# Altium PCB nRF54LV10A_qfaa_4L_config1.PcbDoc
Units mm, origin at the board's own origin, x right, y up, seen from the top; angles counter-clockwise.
Board outline 14.6 x 13 mm, 4 copper layers (Top Layer, Mid-Layer 1, Mid-Layer 2, Bottom Layer), stack 1.64 mm thick; 20 components, 48 nets, 89 pads, 52 vias.
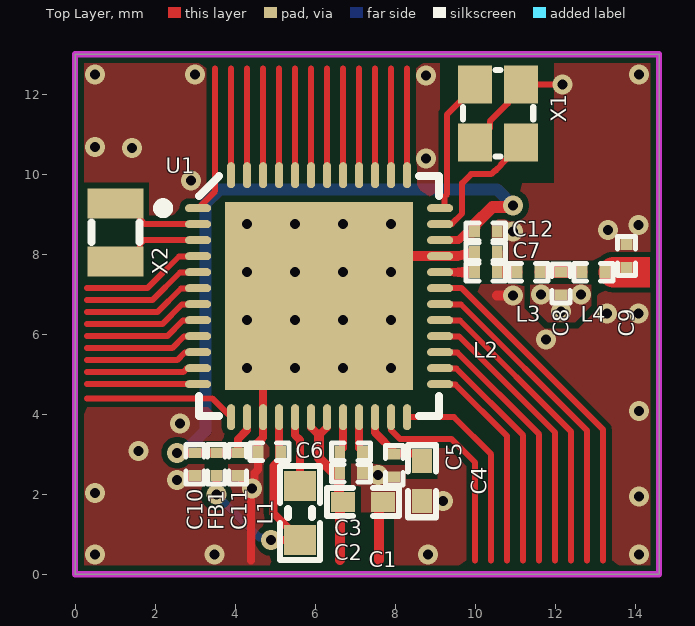
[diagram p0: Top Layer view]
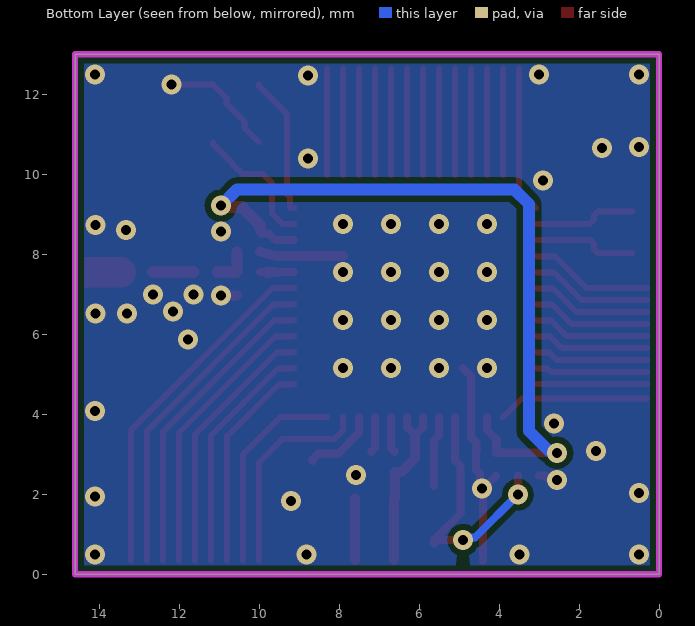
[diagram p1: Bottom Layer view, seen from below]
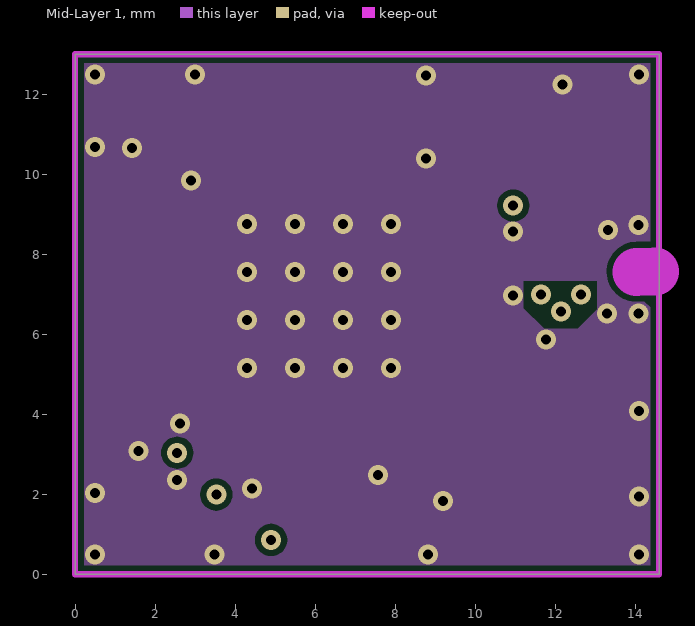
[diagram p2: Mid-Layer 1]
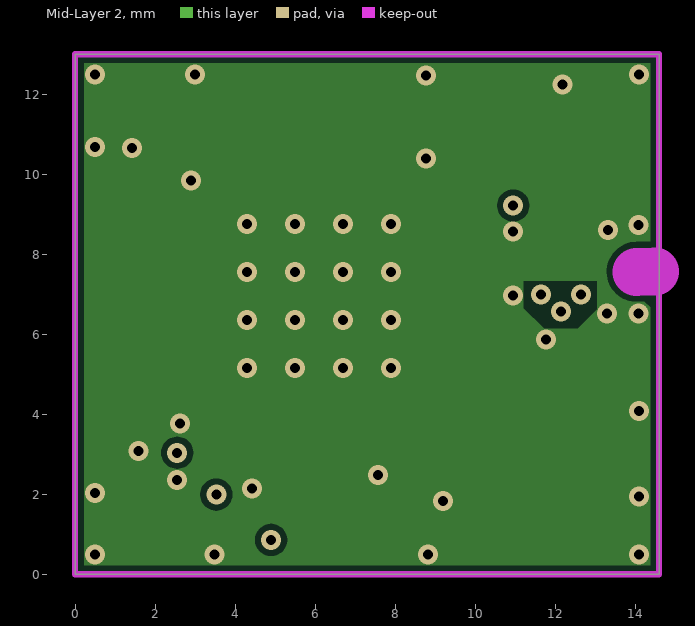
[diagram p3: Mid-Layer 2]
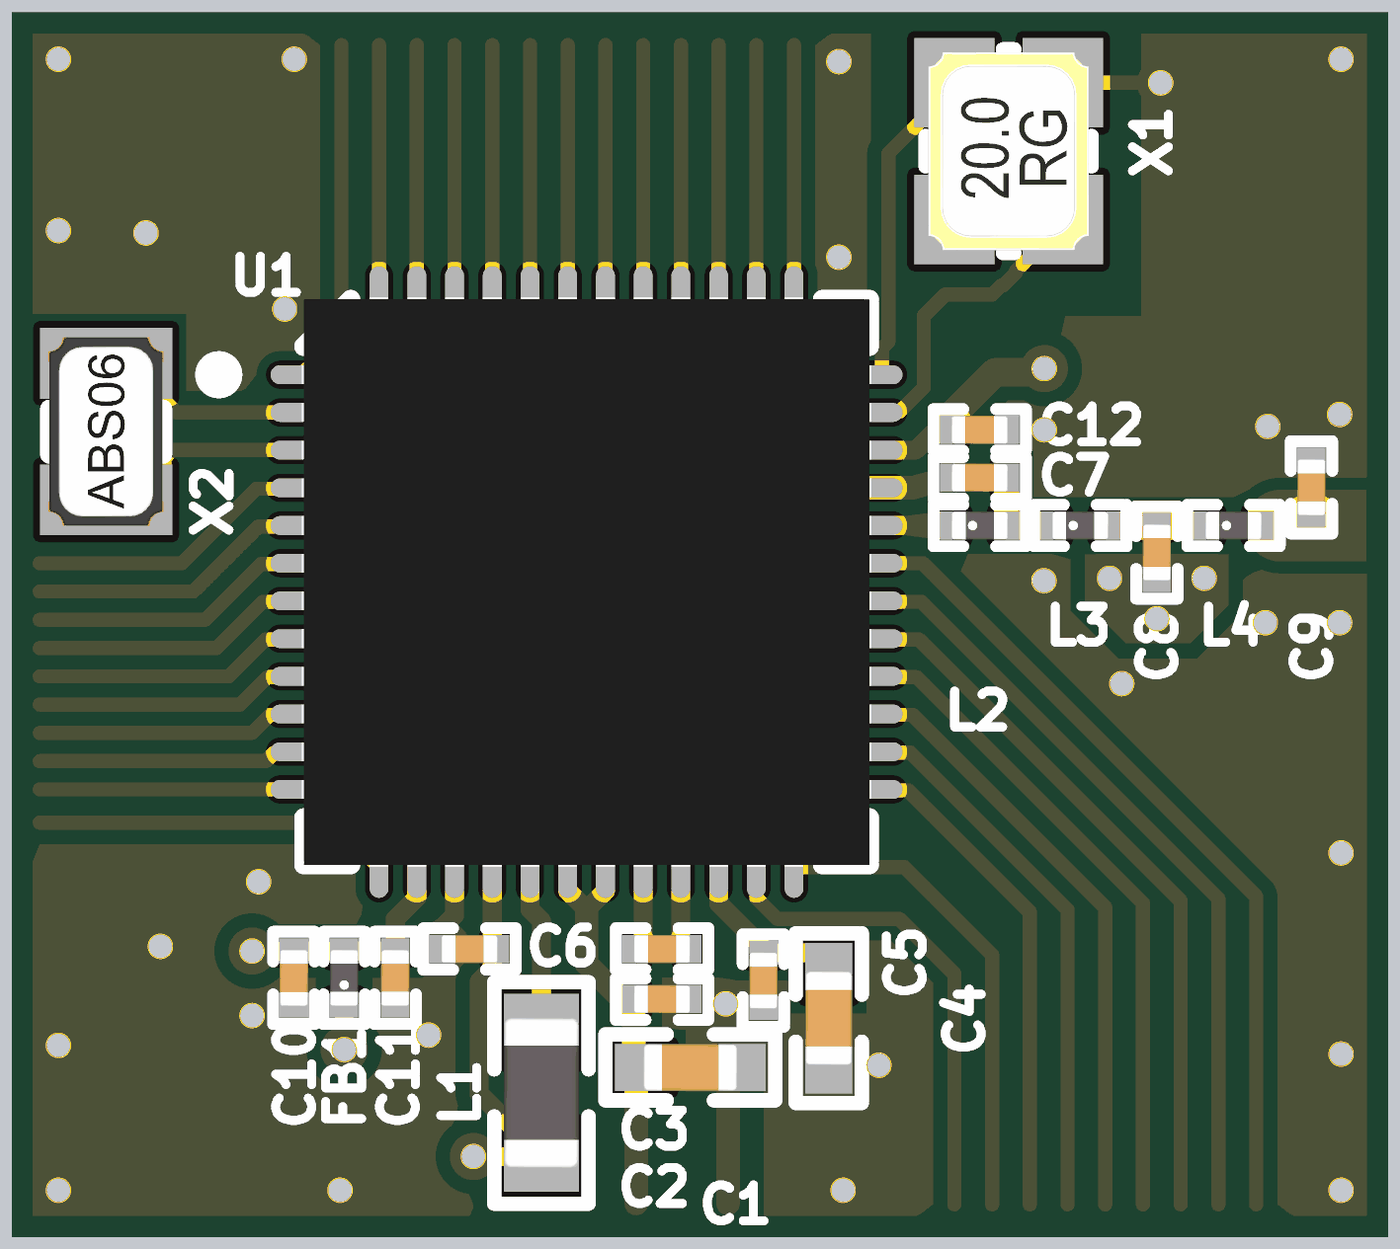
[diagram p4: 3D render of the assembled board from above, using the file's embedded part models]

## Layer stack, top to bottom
Top Solder: solder mask 0.0254, SM-003, Dk 4
Top Layer: signal copper 0.035
Dielectric 1: prepreg 0.1, PP-006, Dk 4.1
Mid-Layer 1: signal copper 0.035
Dielectric1: core 1.3, FR-4, Dk 4.8
Mid-Layer 2: signal copper 0.035
Dielectric 2: prepreg 0.1, PP-006, Dk 4.1
Bottom Layer: signal copper 0.035
Bottom Solder: solder mask 0.0254, SM-003, Dk 4

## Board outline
0,0 14.6,0 14.6,13 0,13

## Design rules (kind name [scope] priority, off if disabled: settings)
Clearance Polygon_ANT [(InNamedPolygon('Mid-Layer1-GND')) or IsFill or IsRegion vs InNet('RF')] p1: gap=0.127 ignorepadtopadclearanceinfootprint=FALSE
Clearance Polygon [(InNamedPolygon('Mid-Layer1-GND')) or (InNamedPolygon('Bottom_Layer-GND'))] p2: gap=0.15 ignorepadtopadclearanceinfootprint=FALSE
Clearance [All] p3: gap=0.15 ignorepadtopadclearanceinfootprint=FALSE
ComponentClearance [All] p1 off: gap=0.254 collisioncheckmode=3 verticalgap=0.254 showdistances=FALSE
FabricationTestPointUsage TestPointUsage [All] p1: valid=0 allowmultiple=FALSE
FabricationTestpoint Testpoint [All] p1: side=3 testpointundercomponent=TRUE minsize=1.016 maxsize=2.54 preferedsize=1.524 minholesize=0 maxholesize=1.016 preferedholesize=0.813 testpointgrid=0.025 allowsidetop=TRUE allowsidebottom=TRUE usegrid=TRUE gridtolerance=0
Height [All] p1 off: minheight=0 maxheight=25.4 prefheight=12.7
HoleSize [All] p1: absolutevalues=TRUE maxlimit=4 minlimit=0.2 maxpercent=80.000 minpercent=20.000
HoleToHoleClearance [All] p1: gap=0.36 allowstackedmicrovias=FALSE
MinimumAnnularRing [All] p1 off: minimumring=0.152
PolygonConnect PolygonConnect_GND_VIAs [isVia and innet(gnd)] p1: connectstyle=Direct reliefconductorwidth=0.254 reliefentries=4 polygonreliefangle="90 Angle" airgapwidth=0.254
PolygonConnect PolygonQFNConnect [HasFootprint('QFN40P600X600X90-48N')] p2: connectstyle=Relief reliefconductorwidth=0.254 reliefentries=4 polygonreliefangle="90 Angle" airgapwidth=0.25
PolygonConnect PolygonDirectConnect [All] p3: connectstyle=Direct reliefconductorwidth=0.254 reliefentries=4 polygonreliefangle="90 Angle" airgapwidth=0.25
RoutingVias [All] p1: holewidth=0.406 width=0.813 viastyle="Through Hole" minholewidth=0.2 minwidth=0.2 maxholewidth=0.711 maxwidth=1.27
SilkToSolderMaskClearance SilkscreenOverComponentPads [IsPad] p1: minsilkscreentomaskgap=0.254 clearancetoexposedcopper=TRUE
SolderMaskExpansion SolderMaskExpansion_via [IsVia] p1: expansion=0.102 istentingtop=TRUE
SolderMaskExpansion [All] p2: expansion=0.076 istentingtop=FALSE
Width [All] p1: maxlimit=2.54 minlimit=0.125 preferedwidth=0.15 midlayer1_minwidth=0.15 midlayer2_minwidth=0.15 minimp=50.000000 maximp=50.000000 favimp=50.000000
23 further rules are at their usual default settings.

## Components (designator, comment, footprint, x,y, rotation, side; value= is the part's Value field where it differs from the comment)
C1 "10µF" CAPC1005X04L 7.2,1.803 r180 top
C2 "100nF" CAPC0603X03L_C#1 6.9,2.528 r180 top
C3 "1.0µF" CAPC0603X03L_C#2 6.9,3.06 r0 top
C4 "10µF" CAPC1005X04L 8.668,2.326 r90 top
C5 "100nF" CAPC0603X03L_C#3 7.975,2.725 r270 top
C6 "4.7µF" CAPC0603X03L_C#1 4.859,3.06 r0 top
C7 "1.5pF" CAPC0603X03L_C#1 10.268,8.06 r0 top
C8 "2.0pF" CAPC0603X03L_C#1 12.147,7.267 r90 top
C9 "0.3pF" CAPC0603X03L_C#1 13.786,7.958 r270 top
C10 "2.2µF" CAPC0603X03L_C#3 2.997,2.753 r270 top
C11 "10nF" CAPC0603X03L_C#1 4.071,2.753 r90 top
C12 "10nF" CAPC0603X03L_C#1 10.268,8.568 r180 top
FB1 "120R/0.2A" INDC0603X03L_C 3.53,2.753 r90 top
L1 "4.7µH" INDC1608X06L 5.621,1.533 r270 top
L2 "2.7nH" INDC0603X03L_C 10.268,7.553 r0 top
L3 "3.5nH" INDC0603X03L_C 11.335,7.553 r0 top
L4 "3.5nH" INDC0603X03L_C 12.96,7.553 r0 top
U1 "nRF54LV10A-QFAA" QFN40P600X600X90-48N 6.1,6.953 r0 top locked
X1 "32MHz" BT-XTAL_2016 10.575,11.525 r90 top
X2 "32.768kHz" XTAL_2012 1.006,8.549 r90 top

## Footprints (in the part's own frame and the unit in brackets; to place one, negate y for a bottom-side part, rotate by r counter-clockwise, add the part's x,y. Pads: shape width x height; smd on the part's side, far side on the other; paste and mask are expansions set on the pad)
BT-XTAL_2016 [mm] "Crystal 2.0 x 1.6 mm"
  rect 0.95x0.85 smd: 1(-0.725,-0.575) 2(0.725,-0.575) 3(0.725,0.575) 4(-0.725,0.575)
  silkscreen extent -1.08,-0.88 1.08,0.88, body extent -1.05,-0.85 1.05,0.85, height 0.56
CAPC0603X03L_C#1 [mm] "Chip Capacitor, 2-Leads, Body 0.6x0.3mm, IPC High Density"
  rect 0.27x0.3 smd mask+0: 1(-0.285,0)
  rect 0.27x0.3 smd mask+0.05: 2(0.285,0)
  silkscreen extent -0.49,-0.22 0.49,0.22, body extent -0.3,-0.15 0.3,0.15, height 0.3
CAPC0603X03L_C#2 [mm] "Chip Capacitor, 2-Leads, Body 0.6x0.3mm, IPC High Density"
  rect 0.27x0.3 smd mask+0.05: 1(-0.285,0) 2(0.285,0)
  silkscreen extent -0.49,-0.22 0.49,0.22, body extent -0.3,-0.15 0.3,0.15, height 0.3
CAPC0603X03L_C#3 [mm] "Chip Capacitor, 2-Leads, Body 0.6x0.3mm, IPC High Density"
  rect 0.27x0.3 smd mask+0.05: 1(-0.285,0)
  rect 0.27x0.3 smd mask+0: 2(0.285,0)
  silkscreen extent -0.49,-0.22 0.49,0.22, body extent -0.3,-0.15 0.3,0.15, height 0.3
CAPC1005X04L [mm] "Chip Capacitor, 2-Leads, Body 1.0x0.5mm, IPC High Density"
  rect 0.6x0.5 smd mask+0: 1(-0.5,0)
  rect 0.6x0.5 smd: 2(0.5,0)
  silkscreen extent -0.9,-0.35 0.9,0.35, body extent -0.5,-0.25 0.5,0.25, height 0.5
INDC0603X03L_C [mm] "Chip Inductor, 2-Leads, Body 0.6x0.3mm, IPC High Density"
  rect 0.27x0.3 smd: 1(-0.285,0) 2(0.285,0)
  silkscreen extent -0.49,-0.22 0.49,0.22, body extent -0.3,-0.15 0.3,0.15, height 0.3
INDC1608X06L [mm] "Chip Inductor, 2-Leads, Body 1.6x0.8mm, IPC High Density"
  rect 0.75x0.8 smd: 1(-0.675,0) 2(0.675,0)
  silkscreen extent -1.17,-0.5 1.17,0.5, body extent -0.8,-0.4 0.8,0.4, height 0.8
QFN40P600X600X90-48N [mm] "QFN, 48-Leads, Body 6,0x6,0mm (max), Pitch 0,40mm, IPC Medium Density"
  oval 0.65x0.2 smd mask+0.05: 1(-3.025,2.2) 2(-3.025,1.8) 3(-3.025,1.4) 4(-3.025,1) 5(-3.025,0.6) 6(-3.025,0.2) 7(-3.025,-0.2) 8(-3.025,-0.6) 9(-3.025,-1) 10(-3.025,-1.4) 11(-3.025,-1.8) 12(-3.025,-2.2) 25(3.025,-2.2) 26(3.025,-1.8) 27(3.025,-1.4) 28(3.025,-1) 29(3.025,-0.6) 30(3.025,-0.2) 31(3.025,0.2) 32(3.025,0.6) 33(3.025,1) 34(3.025,1.4) 35(3.025,1.8) 36(3.025,2.2)
  oval 0.2x0.65 smd mask+0.05: 13(-2.2,-3.025) 14(-1.8,-3.025) 15(-1.4,-3.025) 16(-1,-3.025) 17(-0.6,-3.025) 18(-0.2,-3.025) 19(0.2,-3.025) 20(0.6,-3.025) 21(1,-3.025) 22(1.4,-3.025) 23(1.8,-3.025) 24(2.2,-3.025) 37(2.2,3.025) 38(1.8,3.025) 39(1.4,3.025) 40(1,3.025) 41(0.6,3.025) 42(0.2,3.025) 43(-0.2,3.025) 44(-0.6,3.025) 45(-1,3.025) 46(-1.4,3.025) 47(-1.8,3.025) 48(-2.2,3.025)
  rect 4.7x4.7 smd: 49(0,0)
  silkscreen extent -4.02,-3 3,3, body extent -3.02,-3.02 3.02,3.02, height 0.86
XTAL_2012 [mm] "XTAL SMD 2.0 x 1.2 mm"
  rect 0.75x1.4 smd: 1(-0.725,0) 2(0.725,0)
  silkscreen extent -0.24,-0.6 0.24,0.6, body extent -1,-0.61 1,0.61, height 0.6

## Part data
C1 C4: library part C0402-10µF-6.3V-X6S, "Capacitor, X6S, ±20%, 6.3V", Manufacturer=N.A., Part number NEMS=100200478
C2: library part C0201-100n-10V-X7R, "Capacitor, X7R, ±10%, 100nF, 10V", Manufacturer=N.A., Part number NEMS=100200469
C3: library part C0201-1µ0-6.3V, "Capacitor, Ceramic, X5R, ±20%, 6.3V", Manufacturer=Murata, Manufacturer Part Number=GRM033R60J105MEA2D, Part number IPS=N.A., Part number NEMS=100200387, Supplier Part Number 1=490-7229-1-ND
C5: library part C0201-100n-10V-X7R, "Capacitor, X7R, ±10%", Manufacturer=N.A., Part number NEMS=100200469
C6: library part C0201-4.7µ-6V3-X5R-GRM035R60J475ME15J, "Capacitor, Ceramic, X5R, ±20%, 6.3V", Manufacturer=Murata, Manufacturer Part Number=GRM035R60J475ME15J, Part number IPS=N.A., Part number NEMS=100200685, Supplier Part Number 1=490-GRM035R60J475ME15JDKR-ND
C7: library part C0201-1.5p-25V-NP0-GJM0335C1E1R5WB01, "Capacitor, NP0, ±0.05pF, 25V, High Q", Manufacturer=Murata, Manufacturer Part Number=GJM0335C1E1R5WB01, Part number IPS=N.A., Part number NEMS=100200477, Supplier Part Number 1=490-11176-2-ND
C8: library part C0201-2.0p-HQ-Murata, "Capacitor, NP0, ±0.05pF, 25V", Manufacturer=Murata, Manufacturer Part Number=GJM0335C1E2R0WB01, Part number IPS=00000001775, Part number NEMS=100200419, Part number Norautron=N.A.
C9: library part C0201-0.3p-50V-GRM0335C1HR30BA01, "Capacitor, C0G, ±0.1pF, 50V", Manufacturer=Murata, Manufacturer Part Number=GRM0335C1HR30BA01, Part number IPS=N.A., Part number NEMS=100200650, Supplier Part Number 1=490-6135-2-ND
C10: library part C0201-2µ2-2.5V-X6T-GRM033D80E225ME47D, "Capacitor, Ceramic, 2.2µF 2.5V X6T 0201,±20%", Manufacturer=Murata, Manufacturer Part Number=GRM033D80E225ME47D, Part number IPS=N.A., Part number NEMS=100200527, Supplier Part Number 1=81-GRM033D80E225ME7D
C11 C12: library part C0201-10n-6.3V-X7R, "Capacitor, X7R, 6.3V", Manufacturer=Murata, Manufacturer Part Number=GRM033R70J103KA01D, Part number IPS=N.A., Part number NEMS=100200407, Supplier Part Number 1=490-1262-1-ND
FB1: library part FB0201-120R@100M-200mA-BLM03AG121SN1D, "Ferrite Bead, 120 Ohm @ 100MHz, 200mA, 500 mOhm Max", Manufacturer=Murata, Manufacturer Part Number=BLM03AG121SN1D, Part number IPS=N.A., Part number NEMS=100300419, Supplier Part Number 1=490-5622-1-ND
L1: library part L0603-4µ7-MLZ1608M4R7WT000, "Inductor, 120mA, ±20%, 0.65R", Manufacturer="TDK Corporation", Manufacturer Part Number=MLZ1608M4R7WT000, Part number IPS=N.A., Part number NEMS=100300440, Supplier Part Number 1=445-6390-2-ND
L2: library part L0201-2n7-HQ-Murata, "Inductor, 600mA, ±0.1ｎH, 120mOhm", Manufacturer=Murata, Manufacturer Part Number=LQP03HQ2N7B02, Part number IPS=00000001753, Part number NEMS=100300214, Part number Norautron=N.A., Supplier Part Number 1=490-13909-1-ND
L3 L4: library part L0201-3n5-HQ-Murata, "Inductor, 500mA, ±0.1ｎH, 170mOhm", Manufacturer=Murata, Manufacturer Part Number=LQP03HQ3N5B02, Part number IPS=N.A., Part number NEMS=100300222, Supplier Part Number 1=490-13925-1-ND
U1: "Multi-protocol Bluetooth Low Energy, IEEE 802.15.4 and 2.4GHz proprietary Wireless MCU", Manufacturer="Nordic Semiconductor", Part number IPS=N.A., Part number NEMS=102000335
X1: library part XTAL_SMD2016_32MHz_8pF_Kyocera, "XTAL SMD 2016, 32MHz, Cl=8pF, Tot: ±40ppm", Manufacturer=Kyocera, Manufacturer Part Number=CX2016DB32000D0WZRC1, Part number IPS=00000007827, Part number NEMS=101600039, Part number Norautron=26511136, Supplier Part Number 1=1253-1586-1-ND
X2: library part XTAL_SMD2012_32.768kHz_9pF_TXC, "XTAL SMD 2012, 32.768kHz, 9pF, ±20ppm", Manufacturer="TXC Corporation", Manufacturer Part Number=9HT11-32.768KDZC-T, Part number IPS=N.A., Part number NEMS=101600107, Supplier Part Number 1=887-1426-2-ND

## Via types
v1: diameter 0.5, hole 0.25, Top Layer to Bottom Layer, tented both sides, 52 vias

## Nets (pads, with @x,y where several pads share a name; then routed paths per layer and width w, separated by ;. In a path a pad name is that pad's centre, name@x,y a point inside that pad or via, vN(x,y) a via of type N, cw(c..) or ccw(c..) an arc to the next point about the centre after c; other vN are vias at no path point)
ANT: L2.1 U1.32 | length 0.9
  Top Layer w0.2: U1.32 L2.1 L2.1
DCC: L1.1 U1.17 | length 1.8
  Top Layer w0.2: U1.17 5.5,3.478 5.621,3.357 L1.1
DECA: C10.1 C11.2 C12.2 FB1.2 U1.14 U1.34 | length 19.4
  Top Layer w0.2: U1.34 9.588,8.353 9.758,8.523 9.948,8.523 9.983,8.558 C12.2 C12.2@9.983,8.666
  Top Layer w0.203: v1(2.553,3.038) C11.2 4.071,3.377 4.3,3.606 U1.14
  Top Layer w0.3: C12.2@9.983,8.666 9.983,8.73 10.432,9.18 10.916,9.18 v1(10.954,9.218)
  Bottom Layer w0.3: v1(2.553,3.038) 2.591,3.076 2.748,3.076 3.258,3.585 3.258,9.26 3.616,9.619 10.553,9.619 v1(10.954,9.218)
DECD: C6.2 FB1.1 L1.2 U1.16 | length 6.5
  Top Layer w0.2: v1(3.53,1.992) FB1.1@3.53,2.469 ; v1(4.9,0.858) 5.529,0.858 L1.2@5.621,0.766 ; U1.16 5.1,2.851 4.96,2.711 4.96,1.524 5.617,0.868 L1.2@5.621,0.868
  Bottom Layer w0.2: v1(3.53,1.992) 4.607,0.915 4.833,0.915 4.895,0.853 v1(4.9,0.858)
GND: C1.1 C2.1 C4.1 C5.2 C6.1 C7.1 C8.1 C9.1 C10.2 C11.1 C12.1 U1.15 U1.33 U1.49 X1.2 X1.4 | length 13.1
  Top Layer w0.15: X1.4@10.018,10.809 10.368,11.159 10.368,11.326 10.818,11.776 10.818,11.909 11.168,12.259 X1.2@11.168,12.234 ; X1.2@11.159,12.25 v1(12.187,12.25)
  Top Layer w0.2: v1(2.553,2.353) 2.61,2.41 2.798,2.41 2.855,2.468 C10.2@3,2.468 ; C11.1 v1@4.311,2.228 ; v1@4.311,2.11 v1@4.311,2.268 ; 4.4,0.35 4.4,2.121 v1(4.425,2.146) 4.482,2.203 4.482,2.527 4.574,2.619 C6.1 4.564,3.07 4.564,3.28 4.7,3.416 U1.15 4.7,4.953 U1.49@4.9,5.153 ; v1@4.425,2.028 v1@4.425,2.109
  Top Layer w0.25: 7.6,0.36 C1.1@7.6,1.9 ; U1.49@7.903,7.953 U1.33 9.554,7.953 C7.1@9.981,8.066 ; 10.553,6.967 v1(10.95,6.967)
  other v1: 0.5,0.5 3.486,0.5 8.82,0.5 14.1,0.5 9.2,1.826 14.1,1.945 0.5,2.037 7.575,2.478 1.581,3.088 2.623,3.774 14.1,4.078 4.3,5.153 5.5,5.153 6.7,5.153 7.9,5.153 11.775,5.875 4.3,6.353 5.5,6.353 6.7,6.353 7.9,6.353 13.297,6.522 14.085,6.522 12.147,6.564 11.645,6.993 12.649,6.993 4.3,7.553 5.5,7.553 6.7,7.553 7.9,7.553 10.954,8.568 13.323,8.604 14.085,8.731 4.3,8.753 5.5,8.753 6.7,8.753 7.9,8.753 2.9,9.85 8.775,10.4 1.429,10.657 0.5,10.682 8.775,12.475 0.5,12.5 3,12.5 14.1,12.5
NetC3_1: C3.1 U1.20 | length 0.9
  Top Layer w0.2: C3.1@6.615,3.062 6.615,3.077 6.7,3.162 U1.20
NetC3_2: C3.2 U1.21 | length 0.9
  Top Layer w0.2: U1.21 7.1,3.162 7.185,3.077 C3.2@7.185,3.062
NetC4_2: C4.2 C5.1 U1.22 | length 1.8
  Top Layer w0.2: U1.22 7.5,3.544 C5.1@7.991,3.053 ; C5.1@8.007,3.017 8.518,3.017 8.668,2.867 C4.2
NetC7_2: C7.2 L2.2 L3.1 | length 0.9
  Top Layer w0.27: L2.2@10.553,7.567 C7.2
  Top Layer w0.3: L2.2@10.58,7.552 L3.1@11.03,7.552
NetC8_2: C8.2 L3.2 L4.1 | length 1
  Top Layer w0.3: L3.2@11.64,7.552 12.148,7.552 L4.1@12.656,7.552
NRESET: U1.31 | length 8.8
  Top Layer w0.15: U1.31 9.663,7.153 13.2,3.616 13.2,0.35
P0.00: U1.24 | length 5.1
  Top Layer w0.15: U1.24 9.472,3.928 10.4,3 10.4,0.35
P0.01: U1.25 | length 5.3
  Top Layer w0.15: U1.25 9.135,4.743 9.508,4.743 10.8,3.451 10.8,0.35
P0.02: U1.26 | length 5.9
  Top Layer w0.15: U1.26 9.135,5.143 9.533,5.143 11.2,3.476 11.2,0.35
P0.03: U1.27 | length 6.5
  Top Layer w0.15: U1.27 9.135,5.543 9.557,5.543 11.6,3.5 11.6,0.35
P0.04: U1.28 | length 7.1
  Top Layer w0.15: U1.28 9.135,5.943 9.6,5.943 12,3.543 12,0.35
P1.00/AIN0: U1.39 | length 2.7
  Top Layer w0.15: U1.39@7.5,9.987 7.5,12.65
P1.01/AIN1: U1.40 | length 2.7
  Top Layer w0.15: U1.40@7.1,9.988 7.1,12.65
P1.02/AIN2: U1.41 | length 2.7
  Top Layer w0.15: U1.41 6.7,12.65
P1.03/AIN3: U1.42 | length 2.7
  Top Layer w0.15: U1.42 6.3,12.65
P1.04: U1.44 | length 2.7
  Top Layer w0.15: U1.44 5.5,12.65
P1.05: U1.45 | length 2.7
  Top Layer w0.15: U1.45 5.1,12.65
P1.06: U1.43 | length 2.7
  Top Layer w0.15: U1.43 5.9,12.65
P1.07/AIN4: U1.46 | length 2.7
  Top Layer w0.15: U1.46 4.7,12.65
P1.08: U1.37 | length 2.7
  Top Layer w0.15: U1.37 8.3,12.65
P1.09: U1.38 | length 2.7
  Top Layer w0.15: U1.38 7.9,12.65
P1.10/AIN5: U1.47 | length 2.7
  Top Layer w0.15: U1.47 4.3,12.65
P1.11/AIN6: U1.48 | length 2.7
  Top Layer w0.15: U1.48 3.9,12.65
P1.12/AIN7: U1.1 | length 3.7
  Top Layer w0.15: U1.1 3.5,9.578 3.5,12.65
P1.13/XL1: U1.2 X2.2 | length 2.6
  Top Layer w0.15: X2.2@0.667,9.072 1.528,9.072 1.625,8.975 1.625,8.875 1.747,8.753 U1.2
P1.14/XL2: U1.3 X2.1 | length 2.6
  Top Layer w0.15: X2.1@0.667,8.033 1.533,8.033 1.625,8.125 1.625,8.265 1.713,8.353 U1.3
P1.15: U1.4 | length 3.1
  Top Layer w0.15: 0.302,7.153 1.807,7.153 2.598,7.943 3.065,7.943 U1.4
P1.16: U1.5 | length 3.1
  Top Layer w0.15: 0.302,6.853 1.931,6.853 2.622,7.544 U1.5@3.066,7.544
P1.17: U1.6 | length 3
  Top Layer w0.15: 0.302,6.553 2.056,6.553 2.647,7.144 U1.6@3.066,7.144
P1.18: U1.7 | length 3
  Top Layer w0.15: 0.302,6.253 2.18,6.253 2.671,6.744 U1.7@3.066,6.744
P1.19: U1.8 | length 2.9
  Top Layer w0.15: 0.302,5.953 2.304,5.953 2.695,6.343 3.065,6.343 U1.8
P1.20: U1.9 | length 2.9
  Top Layer w0.15: 0.302,5.653 2.429,5.653 2.719,5.943 3.065,5.943 U1.9
P1.21: U1.10 | length 2.9
  Top Layer w0.15: 0.302,5.353 2.553,5.353 2.743,5.543 3.065,5.543 U1.10
P1.22: U1.11 | length 2.8
  Top Layer w0.15: 0.302,5.053 2.7,5.053 2.79,5.143 3.065,5.143 U1.11
P1.23: U1.12 | length 2.8
  Top Layer w0.15: 0.302,4.753 U1.12
P1.24: U1.13 | length 3.8
  Top Layer w0.15: 0.302,4.4 3.428,4.4 U1.13
P1.25: U1.23 | length 5.2
  Top Layer w0.15: U1.23 7.9,3.603 8.126,3.378 8.712,3.378 ; 8.713,3.378 9.417,3.378 10,2.795 10,0.35
RF: C9.2 L4.2 | length 0.3
  Top Layer w0.762: 13.46,7.552 C9.2@13.722,7.552
SWDCLK: U1.30 | length 8.2
  Top Layer w0.15: U1.30 9.135,6.743 9.649,6.743 12.8,3.592 12.8,0.35
SWDIO: U1.29 | length 7.6
  Top Layer w0.15: U1.29 9.135,6.343 9.624,6.343 12.4,3.568 12.4,0.35
VDDL:nRF: C1.2 C2.2 U1.18 U1.19 | length 4.5
  Top Layer w0.2: U1.18 5.9,3.675 6.1,3.475 6.3,3.675 U1.19
  Top Layer w0.25: 6.1,3.475 6.1,2.901 6.448,2.553 6.605,2.553 6.615,2.543 6.615,2.513 6.6,2.498 C1.2@6.6,1.9 ; C1.2@6.6,1.912 6.627,1.885 6.627,0.36
XC1: U1.35 X1.1 | length 3.4
  Top Layer w0.15: U1.35 9.135,8.762 9.419,8.762 9.675,9.018 9.675,9.776 9.903,10.004 10.404,10.004 10.5,10.1 10.518,10.1 10.65,10.232 10.65,10.25 10.8,10.4 11.15,10.75 X1.1
XC2: U1.36 X1.3 | length 3.5
  Top Layer w0.15: U1.36 9.208,9.153 9.232,9.176 9.232,9.434 9.3,9.502 9.3,11.5 10,12.2 X1.3

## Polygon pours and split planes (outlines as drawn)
GND on Mid-Layer 1 "Mid-Layer1-GND" (solid, remove dead copper, pour order 3): 0,13.025 14.6,13.025 14.6,-0.9 0,-0.9
GND on Mid-Layer 2 "Mid-Layer1-GND" (solid, remove dead copper, pour order 4): 0,13.025 14.6,13.025 14.6,-0.9 0,-0.9
GND on Top Layer "Top_Layer-GND" (solid, remove dead copper, pour order 5): 0,13 14.6,13 14.6,-0.9 0,-0.9
GND on Bottom Layer "Bottom_Layer-GND" (solid, remove dead copper, pour order 2): 0,13.025 0,-0.9 14.6,-0.9 14.6,13.025

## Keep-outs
Mid-Layer 1:
  lines w1.2: 14.033,7.563 14.502,7.575
Mid-Layer 2:
  lines w1.2: 14.033,7.563 14.502,7.575
Keep-Out Layer:
  the board outline again, w0.152

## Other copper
Top Layer:
  rectangle net RF: 13.658,7.171 14.367,7.933
  pour cut-out: 11.981,13.03 11.981,9.775 9.113,9.775 9.113,13.03
  pour cut-out: 11.385,7.244 11.385,6.735 11.817,6.303 12.503,6.303 12.909,6.71 12.908,6.711 12.908,7.244 13.059,7.244 13.059,6.624 12.576,6.141 11.738,6.141 11.23,6.649 11.23,7.244
  pour cut-out: 7.04,0 7.976,0 7.976,1.55 7.04,1.55
  pour cut-out: 7.646,2.885 7.855,2.885 7.855,2.997 7.646,2.997
  pour cut-out: 10.305,8.875 10.305,8.414 10.418,8.414 10.418,8.875
  region net ANT: 9.848,7.702 9.459,7.652 9.459,7.453 9.848,7.402
Mid-Layer 1:
  pour cut-out: 11.219,7.33 11.219,6.655 11.727,6.147 12.565,6.147 13.048,6.63 13.048,7.33
Mid-Layer 2:
  pour cut-out: 11.219,7.33 11.219,6.655 11.727,6.147 12.565,6.147 13.048,6.63 13.048,7.33

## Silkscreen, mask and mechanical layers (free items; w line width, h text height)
Mechanical 1:
  the board outline again, w0.152

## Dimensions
14.6,13 to 14.6,0 on Mechanical 3
0,0 to 14.6,0 on Mechanical 3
